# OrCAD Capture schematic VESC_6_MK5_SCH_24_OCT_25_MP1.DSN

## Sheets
1 PAGE1: size A2
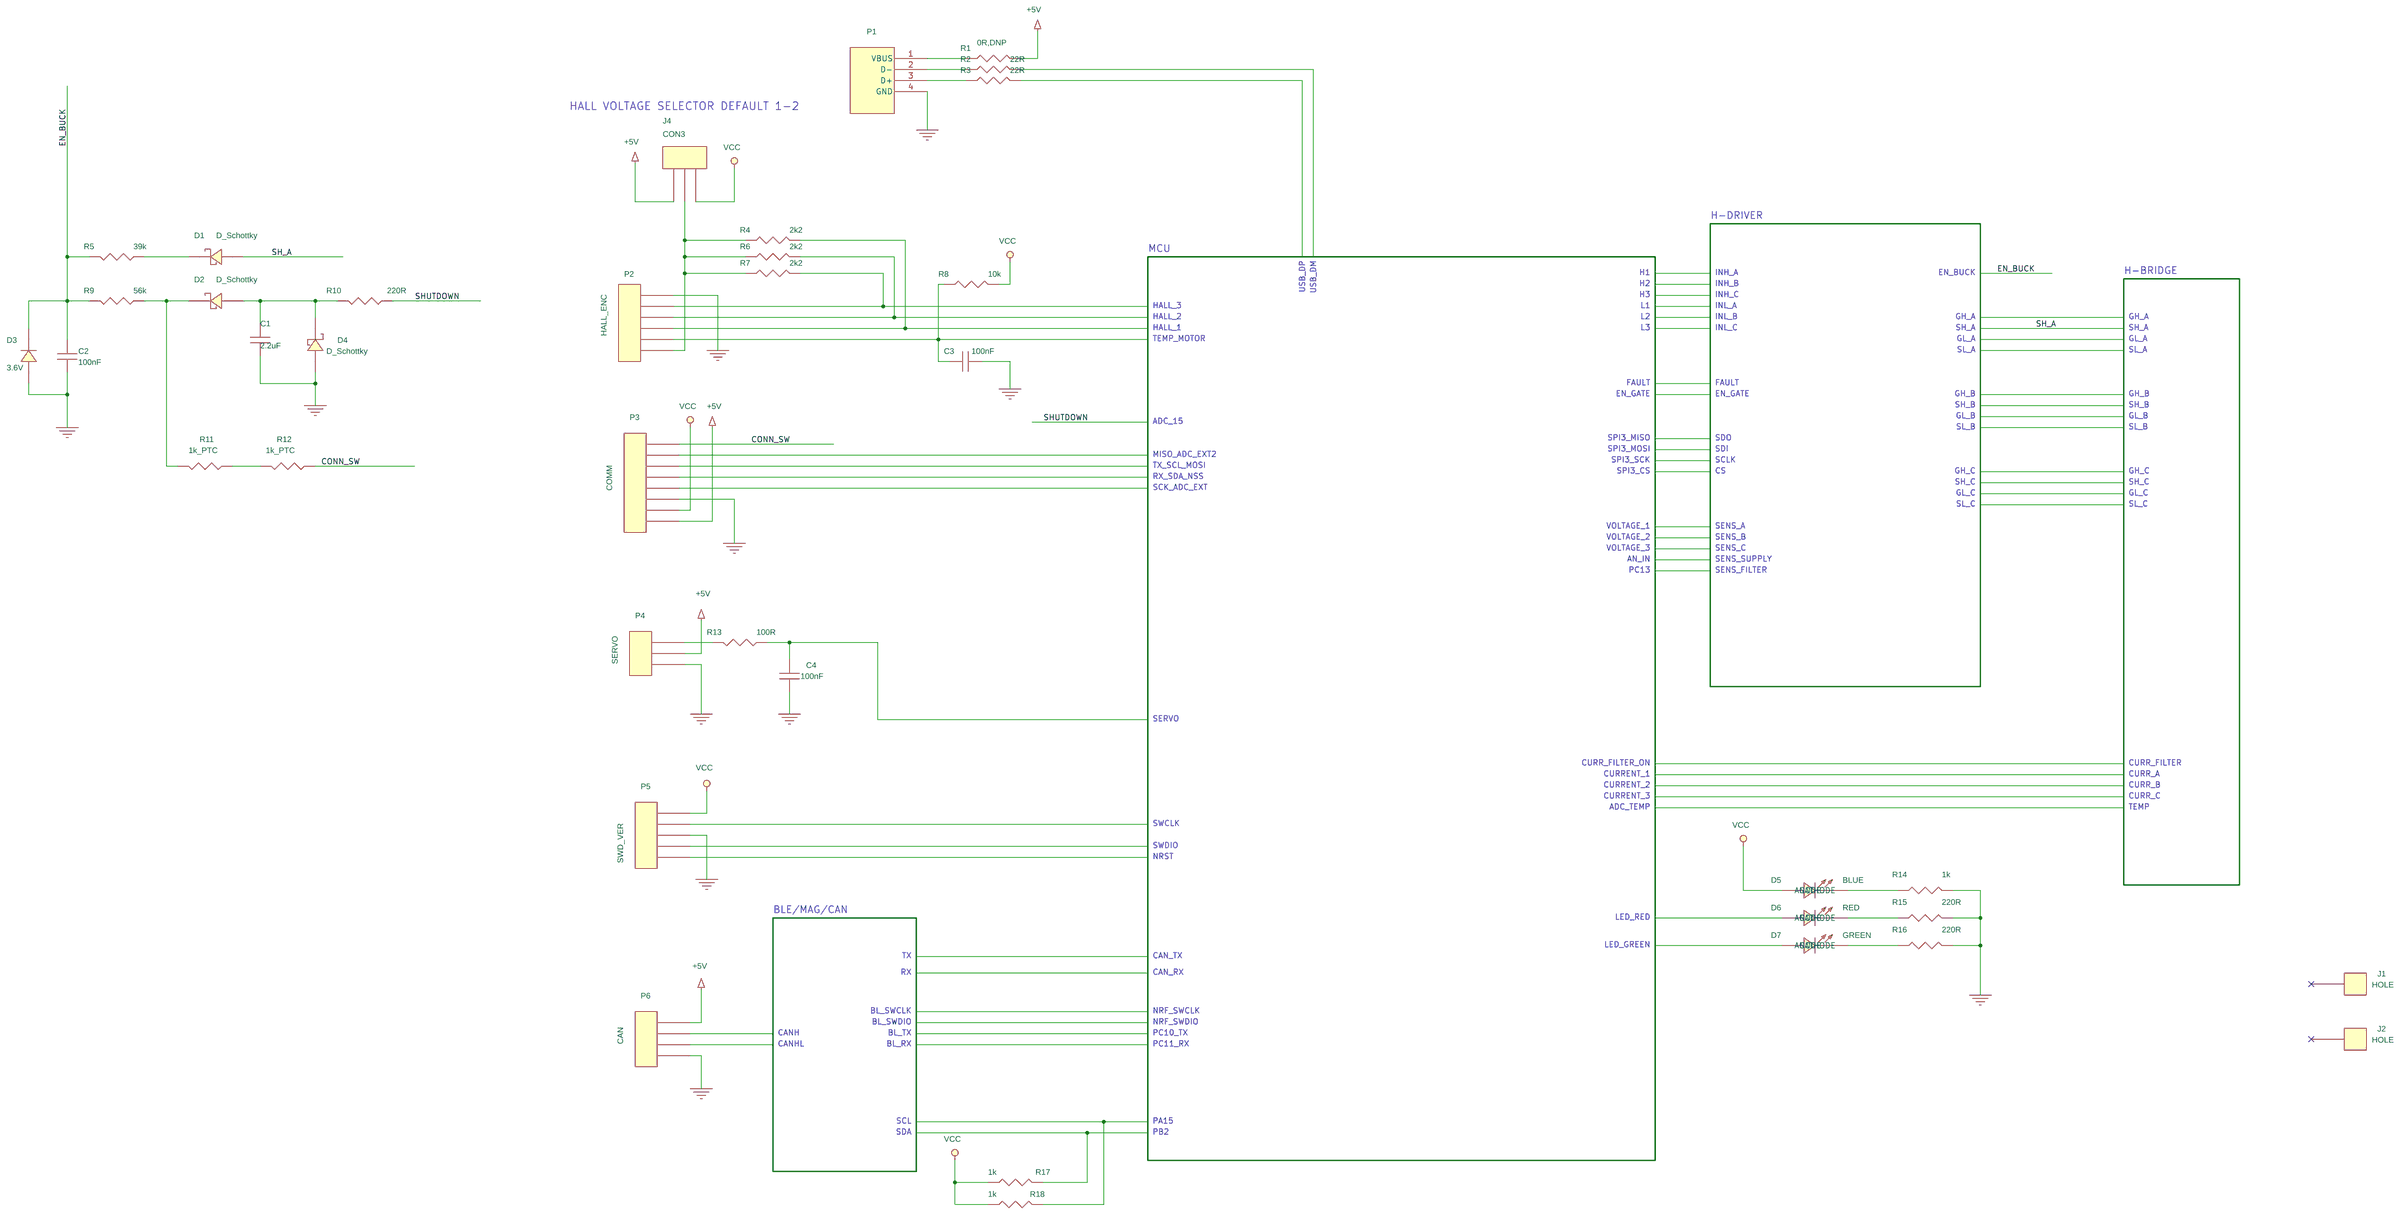
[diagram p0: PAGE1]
2 PAGE4: size A3; block H-BRIDGE
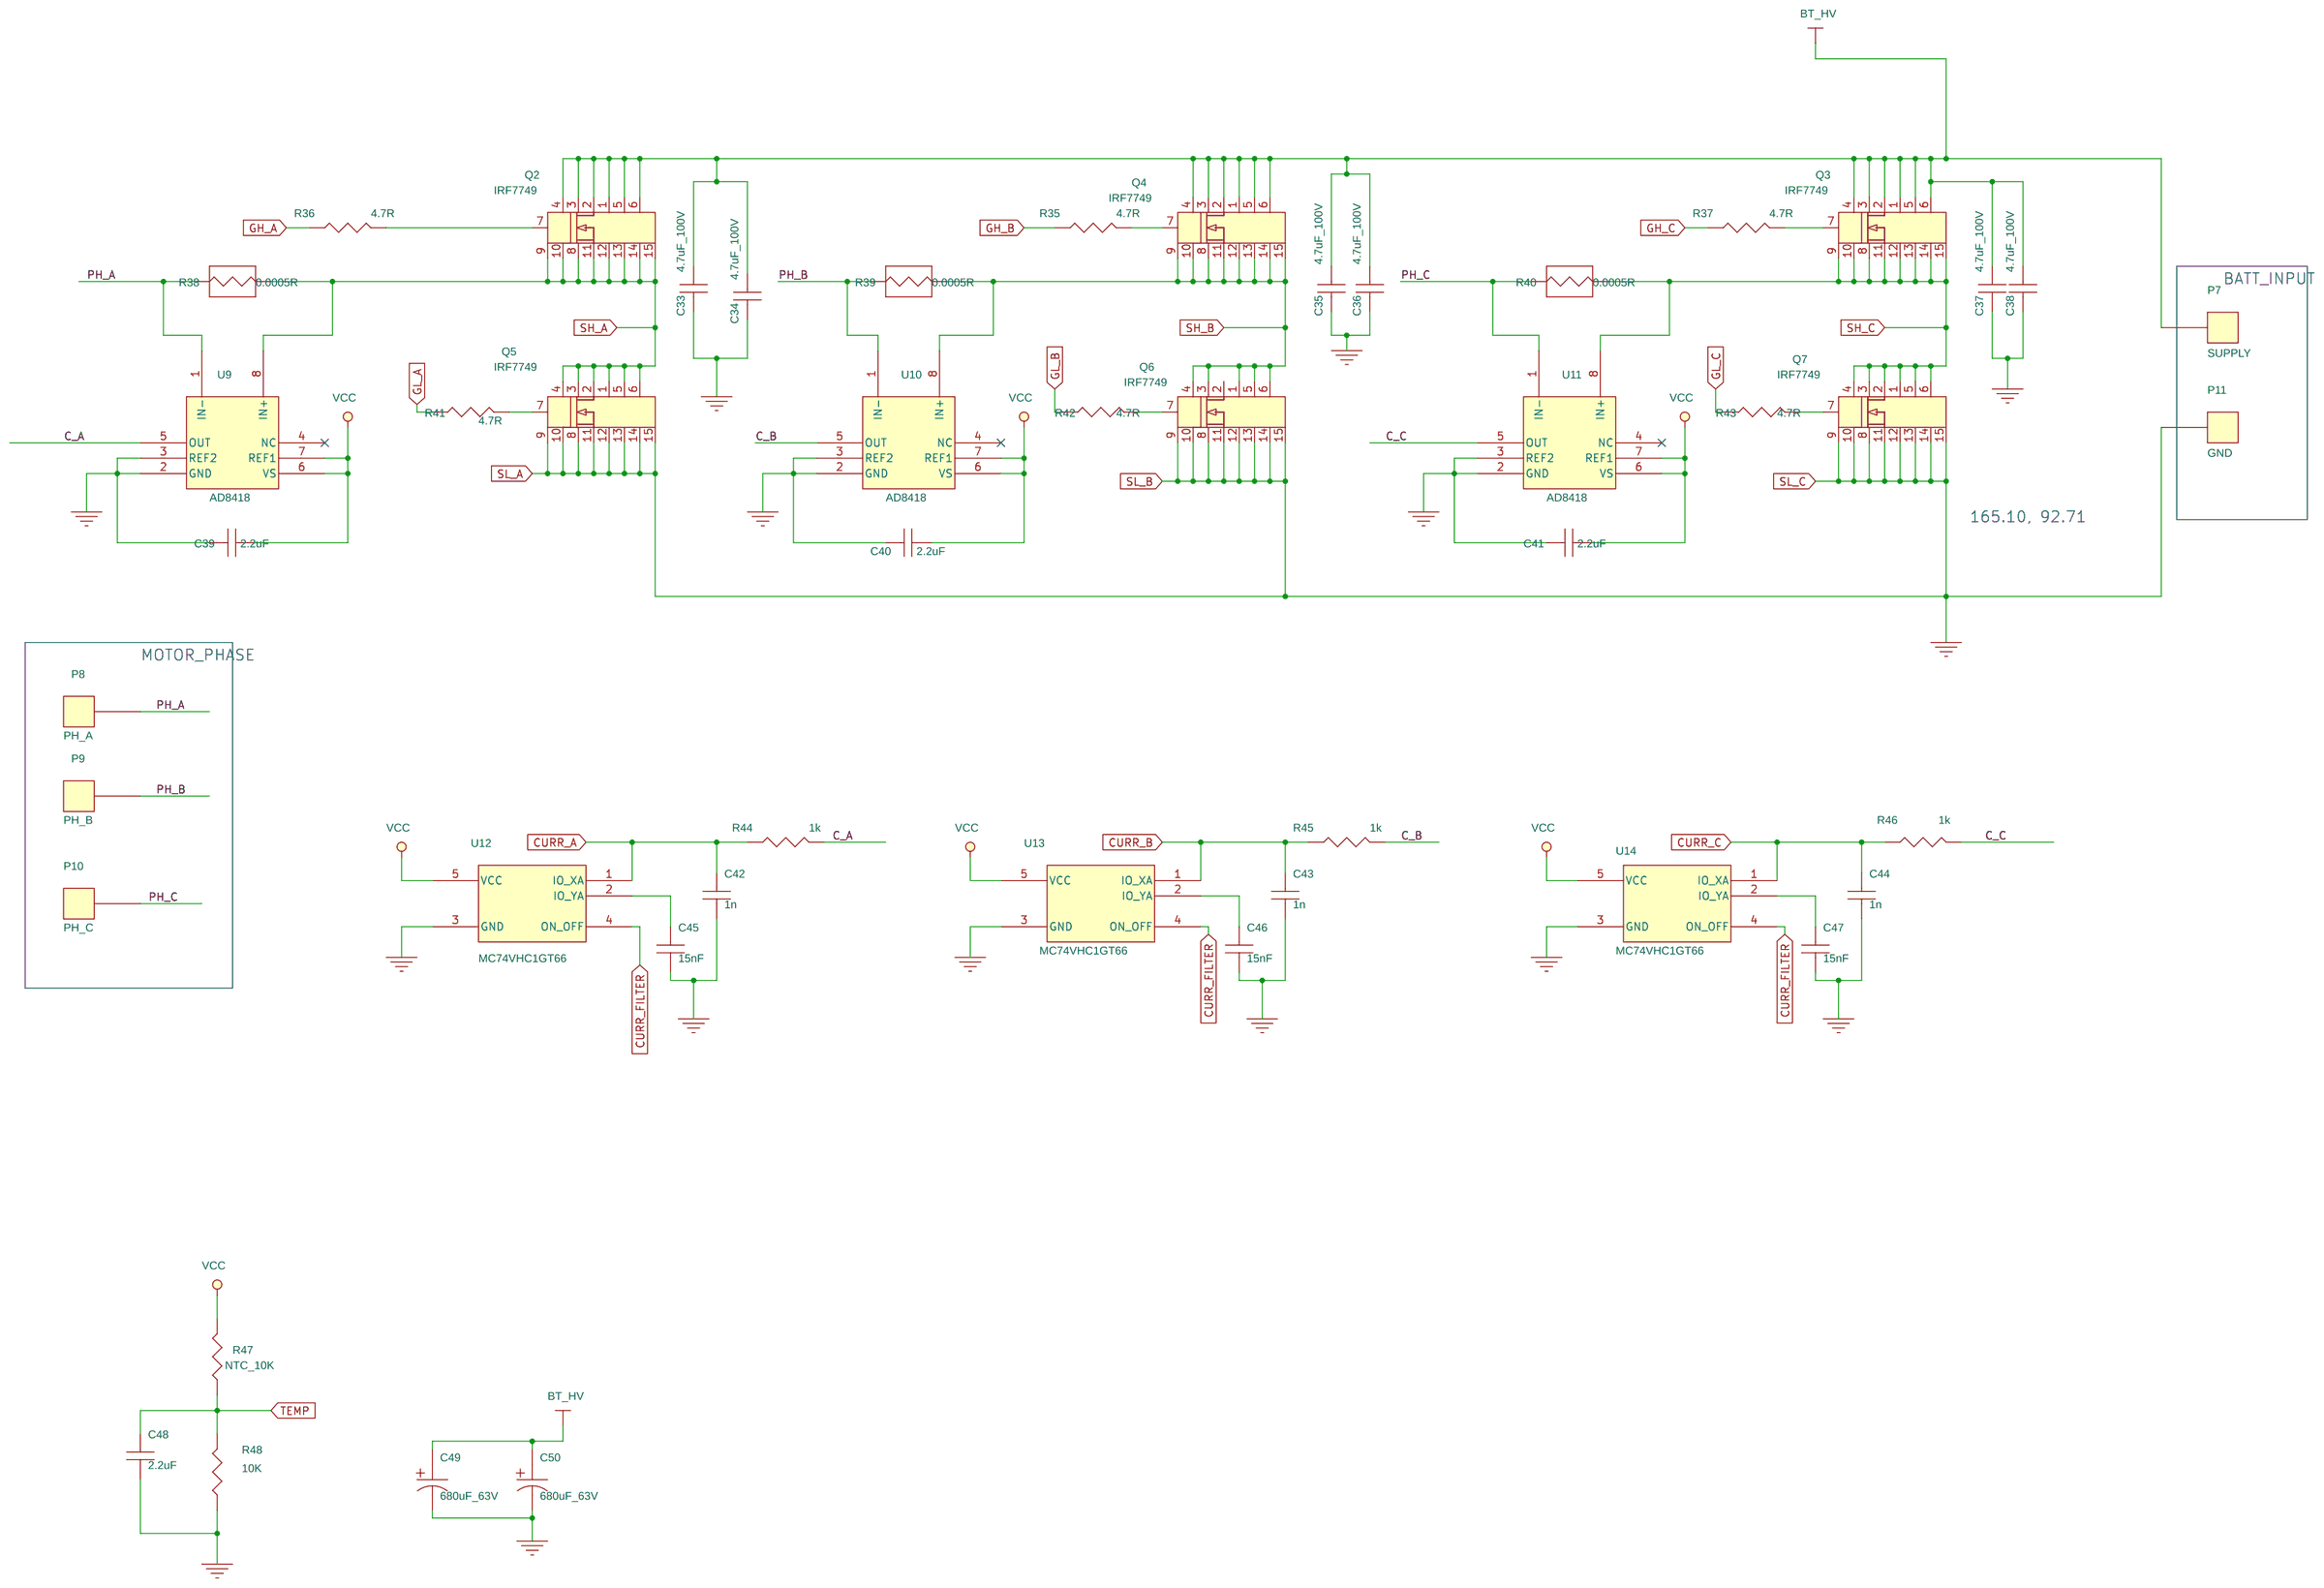
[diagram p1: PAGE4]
3 PAGE3: size A3; block H-DRIVER
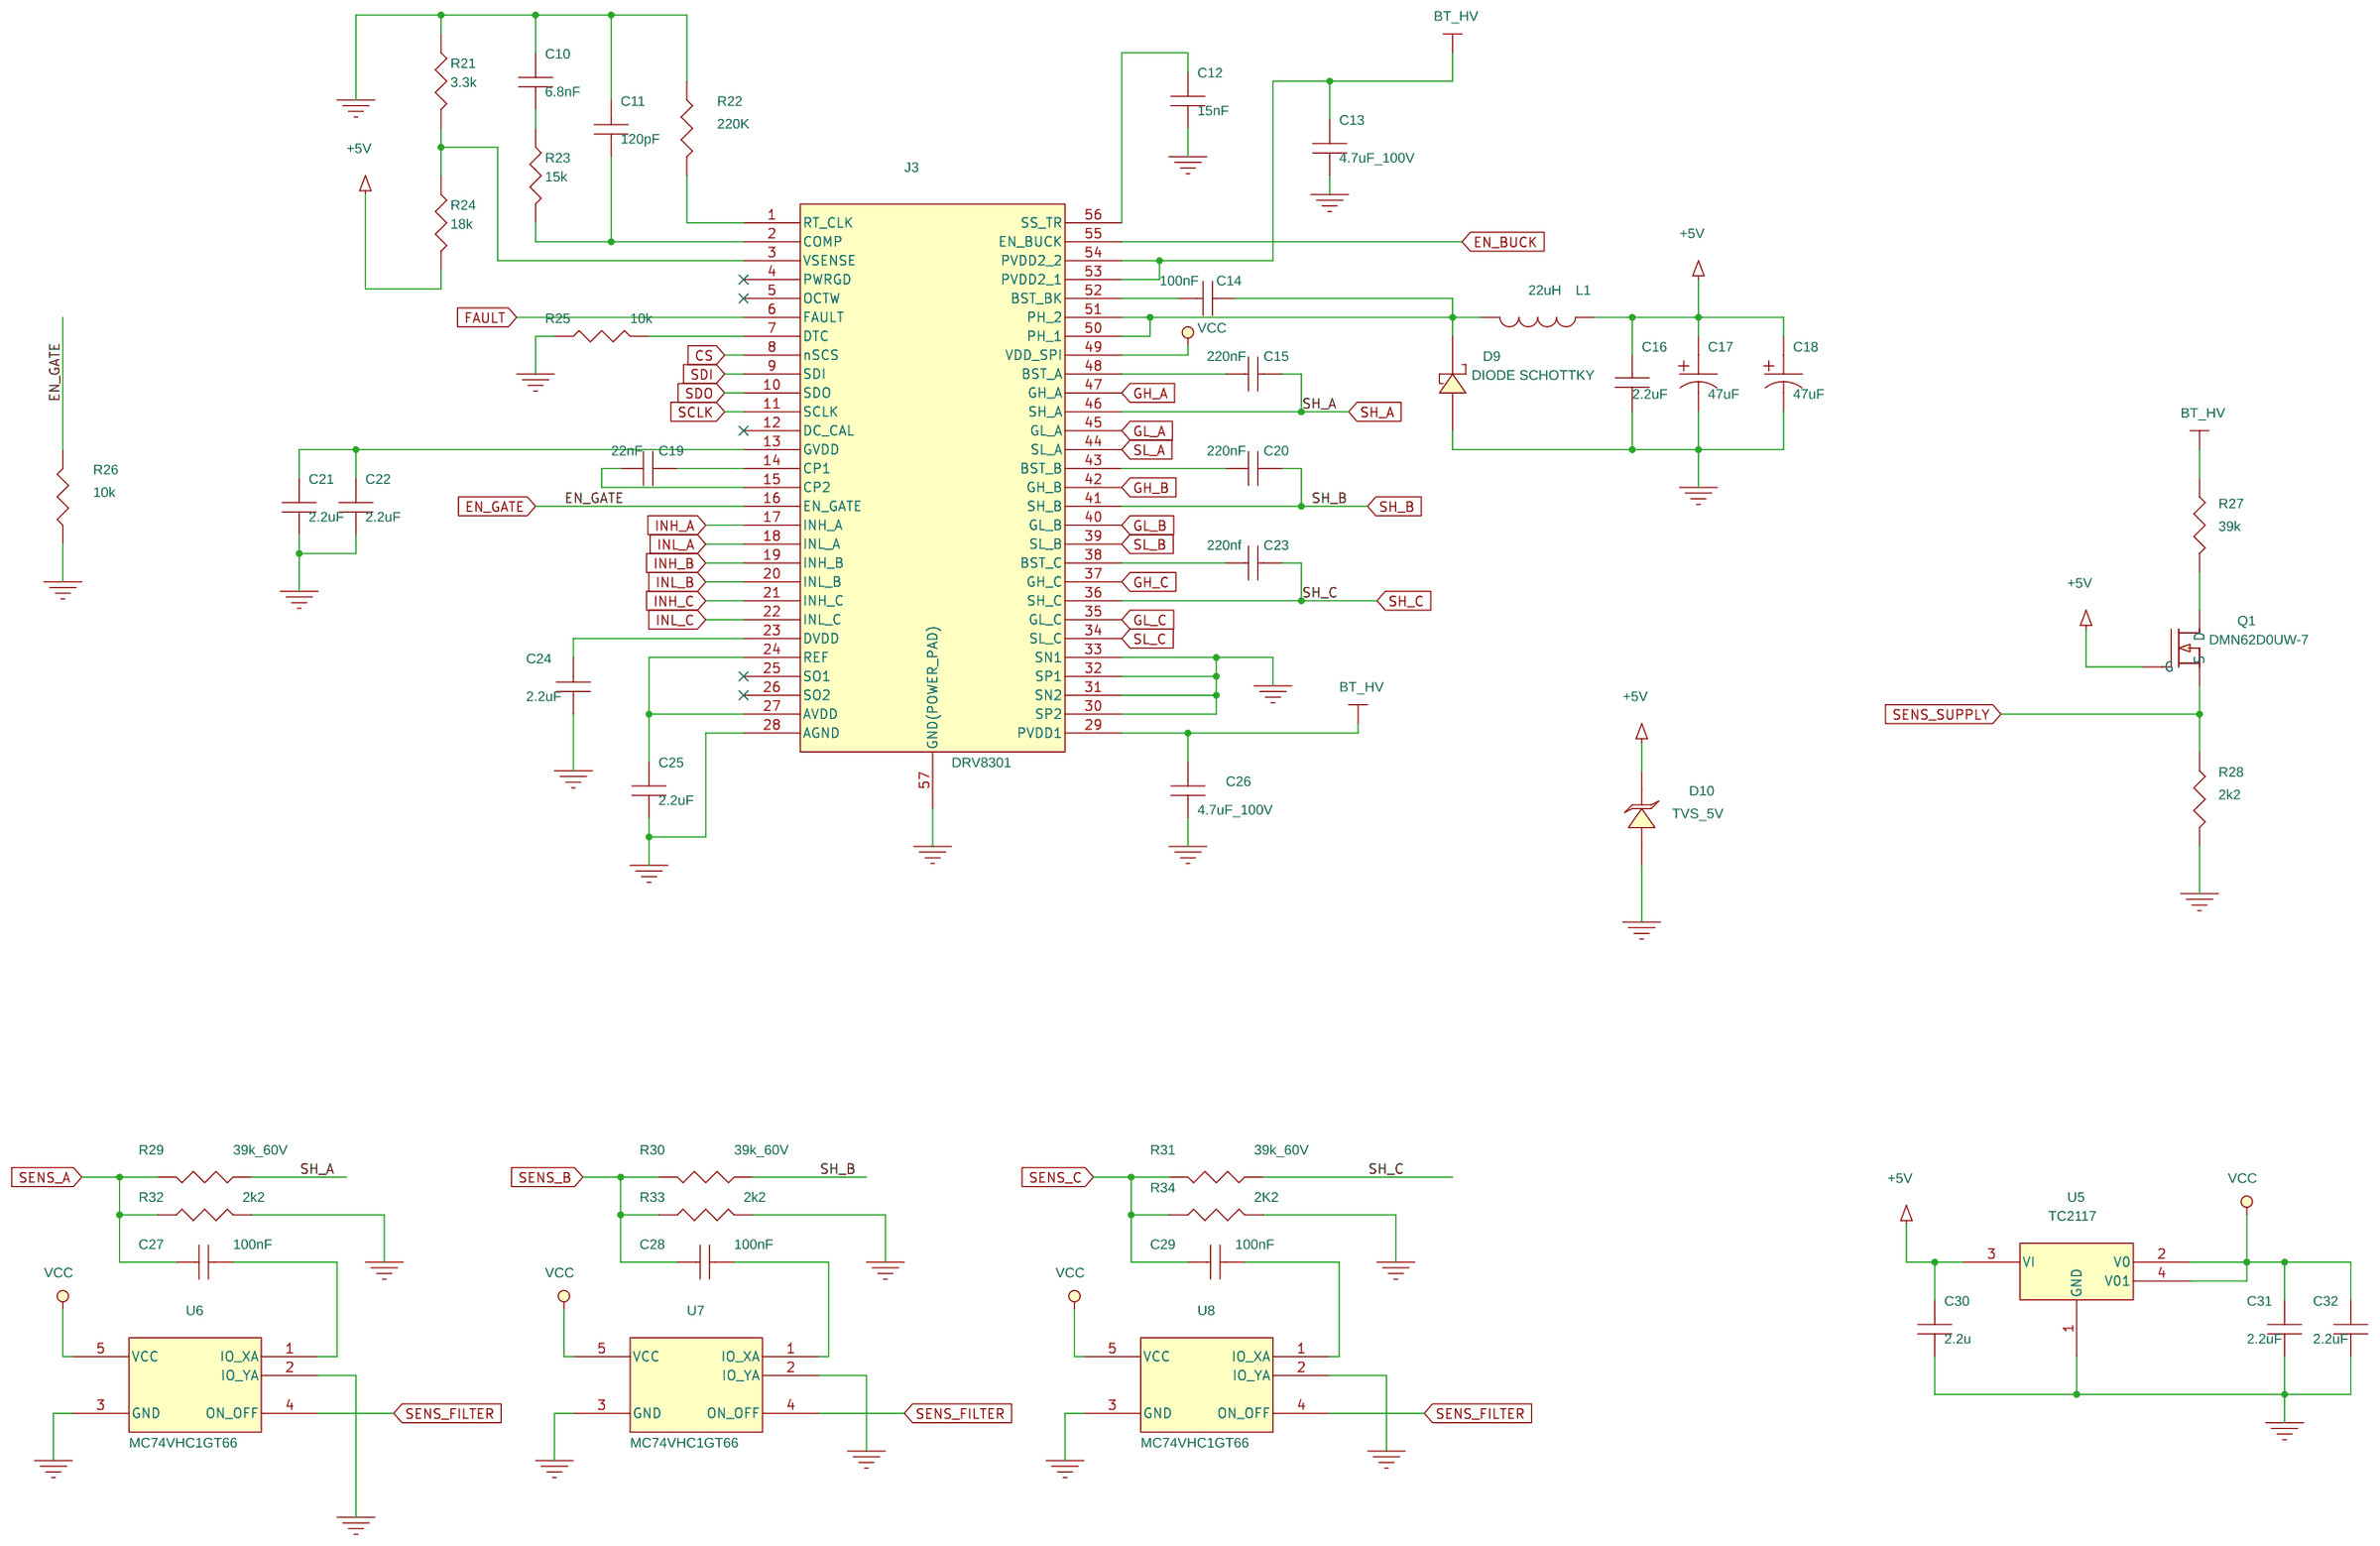
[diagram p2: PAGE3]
4 PAGE5: size A3; block MCU
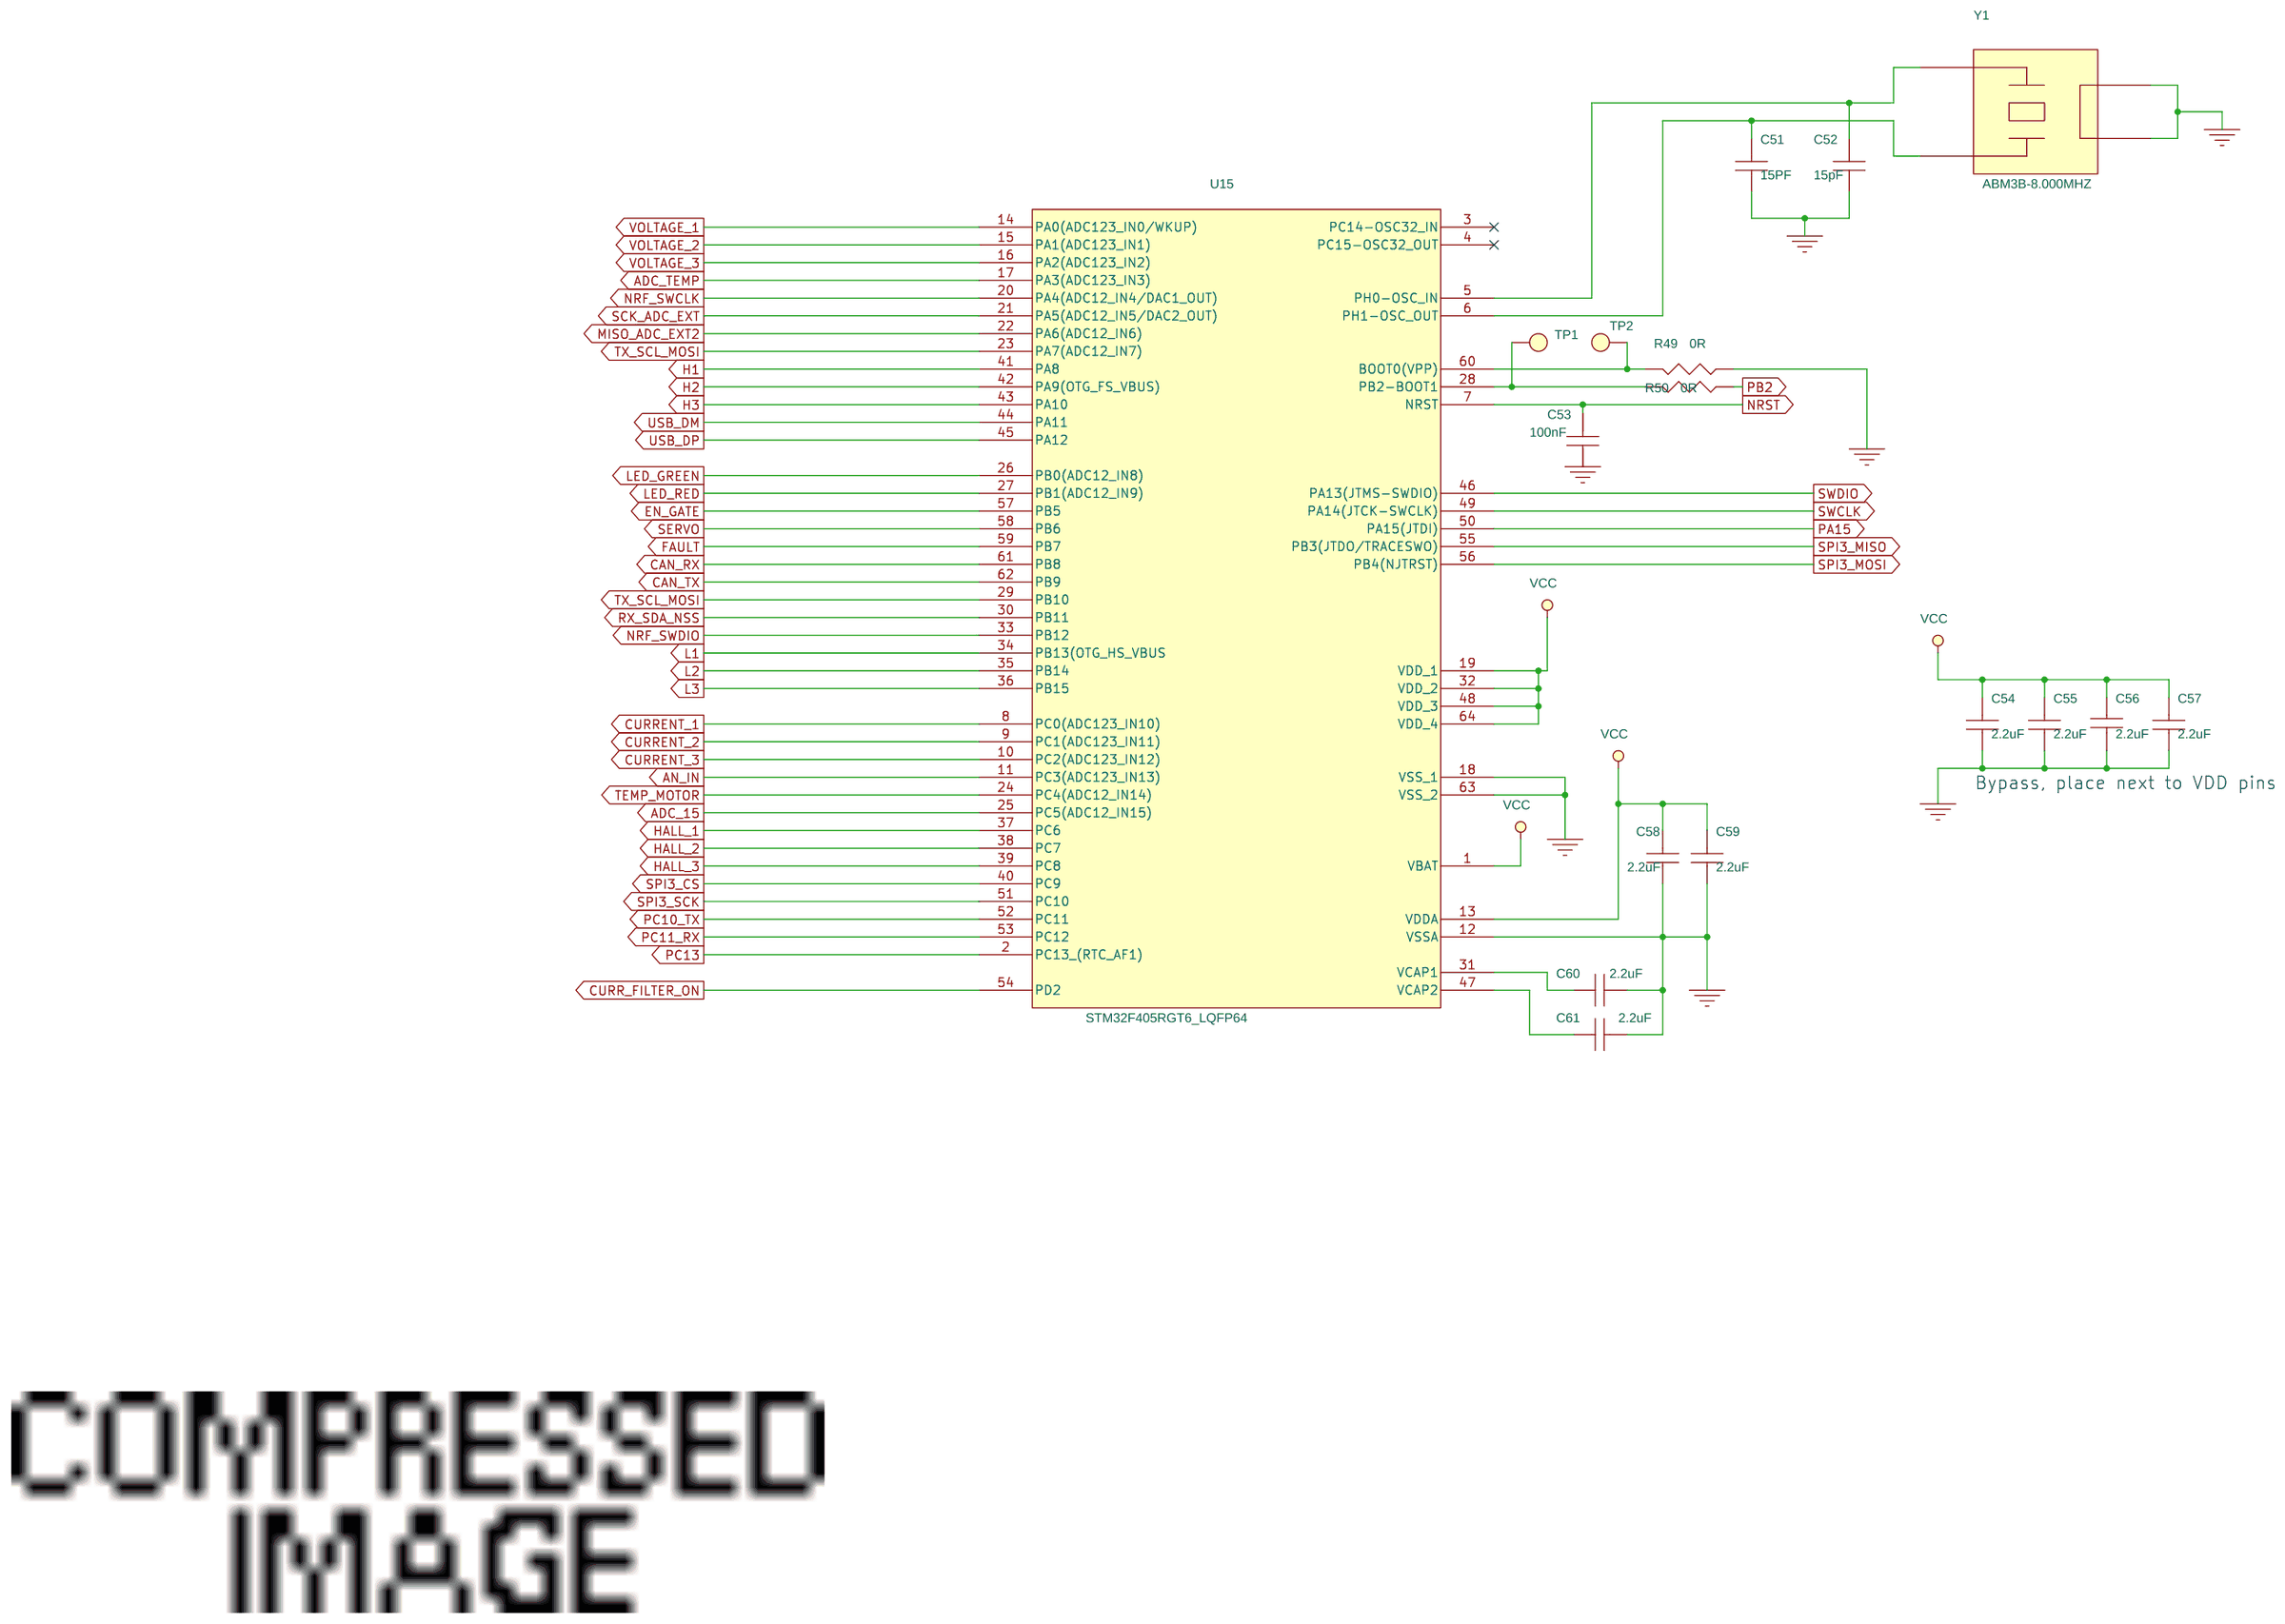
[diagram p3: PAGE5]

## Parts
sheet PAGE1
C1  2.2uF  [0805]
C2  100nF  [0603]
C3  100nF  [0603]
C4  100nF  [0603]
D1  D_Schottky  [SOD_123]
D2  D_Schottky  [SOD_323]
D3  3.6V  [SOD_123]
D4  D_Schottky  [SOD_323]
D5  BLUE  [LED_0603]
D6  RED  [LED_0603]
D7  GREEN  [LED_0603]
J1  HOLE  [MTG_3mm]
J2  HOLE  [MTG_3mm]
J4  CON3  [hdr_1x3]
P1  SWD_VER  [CON_4P_VRT_BM04BGHSTB]
P2  HALL_ENC  [CON_6P_VRT_BM06BGHSTBT]
P3  COMM  [CON_8P_VRT_BM08BGHSTBT]
P4  SERVO  [CON_3P_VRT_BM03BGHSTB]
P5  SWD_VER  [CON_5P_VRT_BM05BGHSTBT]
P6  CAN  [CON_4P_VRT_BM04BGHSTB]
R1  0R,DNP  [0603]
R2  22R  [0603]
R3  22R  [0603]
R4  2k2  [0603]
R5  39k  [0603]
R6  2k2  [0603]
R7  2k2  [0603]
R8  10k  [0603]
R9  56k  [0603]
R10  220R  [0603]
R11  1k_PTC  [0603]
R12  1k_PTC  [0603]
R13  100R  [0603]
R14  1k  [0603]
R15  220R  [0603]
R16  220R  [0603]
R17  1k  [0603]
R18  1k  [0603]
sheet PAGE3
C10  6.8nF  [0603]
C11  120pF  [0603]
C12  15nF  [0603]
C13  4.7uF_100V  [1206]
C14  100nF  [0603]
C15  220nF  [0603]
C16  2.2uF  [0805]
C17  47uF  [cap_8X10]
C18  47uF  [cap_8X10]
C19  22nF  [0603]
C20  220nF  [0603]
C21  2.2uF  [0805]
C22  2.2uF  [0805]
C23  220nf  [0603]
C24  2.2uF  [0805]
C25  2.2uF  [0805]
C26  4.7uF_100V  [1206]
C27  100nF  [0603]
C28  100nF  [0603]
C29  100nF  [0603]
C30  2.2u  [0603]
C31  2.2uF  [0805]
C32  2.2uF  [0805]
D9  DIODE SCHOTTKY  [do214aa]
D10  TVS_5V  [do-214ac]
J3  DRV8301  [HTSSOP_56P_6X14MM]
L1  22uH  [ind_7p8x7p8_sdr0805]
Q1  DMN62D0UW-7  [SOT323_3P]
R21  3.3k  [0603]
R22  220K  [0603]
R23  15k  [0603]
R24  18k  [0603]
R25  10k  [0603]
R26  10k  [0603]
R27  39k  [0603]
R28  2k2  [0603]
R29  39k_60V  [0603]
R30  39k_60V  [0603]
R31  39k_60V  [0603]
R32  2k2  [0603]
R33  2k2  [0603]
R34  2K2  [0603]
U5  TC2117  [sot223_4p]
U6  MC74VHC1GT66  [SC70_5P]
U7  MC74VHC1GT66  [SC70_5P]
U8  MC74VHC1GT66  [SC70_5P]
sheet PAGE4
C33  4.7uF_100V  [1206]
C34  4.7uF_100V  [1206]
C35  4.7uF_100V  [1206]
C36  4.7uF_100V  [1206]
C37  4.7uF_100V  [1206]
C38  4.7uF_100V  [1206]
C39  2.2uF  [0805]
C40  2.2uF  [0805]
C41  2.2uF  [0805]
C42  1n  [0603]
C43  1n  [0603]
C44  1n  [0603]
C45  15nF  [0603]
C46  15nF  [0603]
C47  15nF  [0603]
C48  2.2uF  [0805]
C49  680uF_63V  [ecap_th_12p5x35mm]
C50  680uF_63V  [ecap_th_12p5x35mm]
P7  SUPPLY  [tp_th_120mils]
P8  PH_A  [tp_th_120mils]
P9  PH_B  [tp_th_120mils]
P10  PH_C  [tp_th_120mils]
P11  GND  [tp_th_120mils]
Q2  IRF7749  [IRF7749L1TRPBF]
Q3  IRF7749  [IRF7749L1TRPBF]
Q4  IRF7749  [IRF7749L1TRPBF]
Q5  IRF7749  [IRF7749L1TRPBF]
Q6  IRF7749  [IRF7749L1TRPBF]
Q7  IRF7749  [IRF7749L1TRPBF]
R35  4.7R  [0603]
R36  4.7R  [0603]
R37  4.7R  [0603]
R38  0.0005R  [2512]
R39  0.0005R  [2512]
R40  0.0005R  [2512]
R41  4.7R  [0603]
R42  4.7R  [0603]
R43  4.7R  [0603]
R44  1k  [0603]
R45  1k  [0603]
R46  1k  [0603]
R47  NTC_10K  [0603]
R48  10K  [0603]
U9  AD8418  [msop8]
U10  AD8418  [msop8]
U11  AD8418  [msop8]
U12  MC74VHC1GT66  [SC70_5P]
U13  MC74VHC1GT66  [SC70_5P]
U14  MC74VHC1GT66  [SC70_5P]
sheet PAGE5
C51  15PF  [0603]
C52  15pF  [0603]
C53  100nF  [0603]
C54  2.2uF  [0805]
C55  2.2uF  [0805]
C56  2.2uF  [0805]
C57  2.2uF  [0805]
C58  2.2uF  [0805]
C59  2.2uF  [0805]
C60  2.2uF  [0805]
C61  2.2uF  [0805]
R49  0R  [0603]
R50  0R  [0603]
TP1  T POINT R  [TP_50MIL]
TP2  T POINT R  [TP_50MIL]
U15  STM32F405RGT6_LQFP64  [lqfp64_10x10mm]
Y1  ABM3B-8.000MHZ  [XTAL_4P_5X3P2MM_ABM3B]

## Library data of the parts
C1 C16 C21 C22 C24 C25 C31 C32 C39-C41 C48 C54-C61 = CAP_NP: Manufacturer: TDK; Mfg_Num: C2012X7R1H225K125AE
C2-C4 C10-C12 C14 C15 C19 C20 C23 C27-C30 C42-C47 C53 = CAP_NP
D1 = DIODE_SCHOTTKY_0: Manufacturer: onsemi; Mfg_Num: MMSD4148T1G
D2 D4 = DIODE_SCHOTTKY_0: Manufacturer: Diodes Incorporated; Mfg_Num: BAT54WS
D3 = DIODE31_0: Manufacturer: Diodes Incorporated; Mfg_Num: MMSZ5232B
D5-D7 = LED_3
J1 J2 P7-P11 = CON1
J4 = CON3_1
P1 = CON6A_8: Manufacturer: JST Sales America Inc.; Mfg_Num: BM04B-GHS-TBT
P2 = CON6_0: Mfg_Num: BM06B-GHS-TBT
P3 = CON8: Mfg_Num: BM08B-GHS-TBT
P4 = CON3: Mfg_Num: BM03B-GHS-TBT
P5 = CON5: Manufacturer: JST Sales America Inc.; Mfg_Num: BM05B-GHS-TBT
P6 = CON4_0: Mfg_Num: BM04B-GHS-TBT
R1-R18 R21-R37 R41-R50 = R
C13 C26 C33-C38 = CAP_NP: Manufacturer: Murata Electronics; Mfg_Num: GRJ31CZ72A475ME01L
C17 C18 = CAP_POL_0: Manufacturer: Nichicon; Mfg_Num: UCX1H470MCL1GS
D9 = DIODE_SCHOTTKY_1: Manufacturer: Nexperia; Mfg_Num: PMEG6020ER,115
D10 = DIODE_TVS_0: Manufacturer: Littelfuse; Mfg_Num: SMAJ5.0A
J3 = CON58_3: Manufacturer: Texas Instruments; Mfg_Num: DRV8301DCAR
L1 = INDUCTOR: Manufacturer: Bourns; Mfg_Num: SDR0805-220ML
Q1 = MOSFET_N_3: Manufacturer: Diodes Incorporated
U5 = CON2AP_4: Manufacturer: Microchip Technology; Mfg_Num: TC2117-3.3VDBTR
U6-U8 U12-U14 = CON6A_5: Manufacturer: onsemi; Mfg_Num: MC74VHC1GT66DFT1
C49 C50 = CAP_POL_0: Mfg_Num: EKY630ELL681MK40S
Q2-Q4 Q7 = MOSFET_N_5: Manufacturer: Infineon
Q5 Q6 = MOSFET_N_5: Manufacturer: Infineon; Mfg_Num: IRF7749L1TRPB
R38-R40 = R_3: Manufacturer: Bourns; Mfg_Num: CSS2H-2512R-L500F
U9-U11 = CON8A_5: Manufacturer: Analog Devices Inc; Mfg_Num: AD8418AWBRMZ
C51 C52 = CAP_NP: Manufacturer: Murata Electronics; Mfg_Num: GRM1885C2A150JA01D
TP1 TP2 = T_POINT_R
U15 = CON60_5: Manufacturer: STMicroelectronics
Y1 = CRYSTAL1-4_SM_9: Manufacturer: ABRACON; Mfg_Num: ABM3B-8.000MHZ-10-1-U-T

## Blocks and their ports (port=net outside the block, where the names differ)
H-BRIDGE = schematic H-Bridge, on sheet PAGE1: GL_A=N483651, SH_A, SL_A=0, SH_B=N496273, GL_B=N496277, SL_B=0, SH_C=N496289, GH_C=N496285, SL_C=0, GL_C=N496293, GH_B=N496269, CURR_C=N495765, CURR_B=N495753, CURR_A=N495741, CURR_FILTER=N495729, TEMP=N495777, GH_A=N483635
MCU = schematic MCU, on sheet PAGE1: SCK_ADC_EXT=N492258, MISO_ADC_EXT2=N492162, TX_SCL_MOSI=N492166, H1=N494356, H2=N494360, VOLTAGE_1=N495709, VOLTAGE_2=N495713, VOLTAGE_3=N495717, ADC_TEMP=N495777, NRF_SWCLK=N490496, H3=N494364, USB_DM=N421455, USB_DP=N421471, LED_GREEN=N317096, CAN_TX=N490262, RX_SDA_NSS=N492170, NRF_SWDIO=N490506, L1=N494368, LED_RED=N317032, EN_GATE=N494760, SERVO=N119428, FAULT=N494756, CAN_RX=N490274, L2=N494372, L3=N494376, CURRENT_1=N495741, CURRENT_2=N495753, HALL_2=N114106, HALL_3=N114102, SPI3_CS=N495168, SPI3_SCK=N495164, PC10_TX=N490510, CURRENT_3=N495765, AN_IN=N495721, TEMP_MOTOR=N114114, ADC_15=SHUTDOWN, HALL_1=N114110, PC11_RX=N490514, PC13=N495725, CURR_FILTER_ON=N495729, SWDIO=N316068, SWCLK=N316048, PA15=N488738, SPI3_MISO=N495156, SPI3_MOSI=N495160, NRST=N316080, PB2=N488742
BLE/MAG/CAN = schematic , on sheet PAGE1: SDA=N488742, SCL=N488738, TX=N490262, RX=N490274, CANH=N488558, CANHL=N488562, BL_TX=N490510, BL_RX=N490514, BL_SWCLK=N490496, BL_SWDIO=N490506
H-DRIVER = schematic Driver, on sheet PAGE1: FAULT=N494756, CS=N495168, SDI=N495160, SDO=N495156, SCLK=N495164, EN_GATE=N494760, INH_A=N494356, INL_A=N494368, INH_B=N494360, INL_B=N494372, INH_C=N494364, INL_C=N494376, EN_BUCK, GH_A=N483635, GL_A=N483651, SL_A=0, GH_B=N496269, GL_B=N496277, SL_B=0, GH_C=N496285, GL_C=N496293, SL_C=0, SH_C=N496289, SH_B=N496273, SH_A, SENS_A=N495709, SENS_B=N495713, SENS_C=N495717, SENS_FILTER=N495725, SENS_SUPPLY=N495721

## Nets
+5V: C16.1 C17.P C18.P C30.2 D10.K(CATHODE) J4.1 L1.1 P3.1 P4.2 P6.4 Q1.1(G) R1.2 R24.2 U5.3(VI)
VCC: C31.2 C32.2 C39.2 C40.2 C41.2 C54.2 C55.2 C56.1 C57.2 C58.2 C59.2 D5.A(ANODE) J3.49(VDD_SPI) J4.3 P3.2 P5.5 R8.2 R17.2 R18.2 R47.2 U5.2(V0) U5.4(V01) U6.5(VCC) U7.5(VCC) U8.5(VCC) U9.6(VS) U9.7(REF1) U10.6(VS) U10.7(REF1) U11.6(VS) U11.7(REF1) U12.5(VCC) U13.5(VCC) U14.5(VCC) U15.1(VBAT) U15.13(VDDA) U15.19(VDD_1) U15.32(VDD_2) U15.48(VDD_3) U15.64(VDD_4)
0: C1.1 C2.1 C3.2 C4.1 C10.2 C11.2 C12.1 C13.1 C16.2 C17.N C18.N C21.1 C22.1 C24.1 C25.1 C26.1 C30.1 C31.1 C32.1 C33.2 C34.2 C35.2 C36.2 C37.2 C38.2 C39.1 C40.1 C41.1 C42.2 C43.2 C44.2 C45.2 C46.2 C47.2 C48.2 C49.N C50.N C51.1 C52.1 C53.1 C54.1 C55.1 C56.2 C57.1 C58.1 C59.1 C60.2 C61.2 D3.A D4.A(ANODE) D9.A(ANODE) D10.A(ANODE) J3.28(AGND) J3.30(SP2) J3.31(SN2) J3.32(SP1) J3.33(SN1) J3.34(SL_C) J3.39(SL_B) J3.44(SL_A) J3.57(GND(POWER_PAD)) P1.4(GND) P2.1 P3.3 P4.1 P5.3 P6.1 P11.1 Q5.8(S1) Q5.9(S2) Q5.10(S3) Q5.11(S4) Q5.12(S5) Q5.13(S6) Q5.14(S7) Q5.15(S8) Q6.8(S1) Q6.9(S2) Q6.10(S3) Q6.11(S4) Q6.12(S5) Q6.13(S6) Q6.14(S7) Q6.15(S8) Q7.8(S1) Q7.9(S2) Q7.10(S3) Q7.11(S4) Q7.12(S5) Q7.13(S6) Q7.14(S7) Q7.15(S8) R14.2 R15.2 R16.2 R21.1 R22.1 R25.1 R26.1 R28.2 R32.2 R33.2 R34.2 R48.1 R49.1 U5.1(GND) U6.2(IO_YA) U6.3(GND) U7.2(IO_YA) U7.3(GND) U8.2(IO_YA) U8.3(GND) U9.2(GND) U9.3(REF2) U10.2(GND) U10.3(REF2) U11.2(GND) U11.3(REF2) U12.3(GND) U13.3(GND) U14.3(GND) U15.12(VSSA) U15.18(VSS_1) U15.63(VSS_2) Y1.2 Y1.4
BT_HV: C13.2 C26.2 C33.1 C34.1 C35.1 C36.1 C37.1 C38.1 C49.P C50.P J3.29(PVDD1) J3.53(PVDD2_1) J3.54(PVDD2_2) P7.1 Q2.1(D1) Q2.2(D2) Q2.3(D3) Q2.4(D4) Q2.5(D5) Q2.6(D6) Q3.1(D1) Q3.2(D2) Q3.3(D3) Q3.4(D4) Q3.5(D5) Q3.6(D6) Q4.1(D1) Q4.2(D2) Q4.3(D3) Q4.4(D4) Q4.5(D5) Q4.6(D6) R27.1
CONN_SW: P3.8 R12.1
EN_BUCK: C2.2 D3.K J3.55(EN_BUCK) R5.2 R9.2
H-BRIDGE/C_A: R44.2 U9.5(OUT)
H-BRIDGE/C_B: R45.2 U10.5(OUT)
H-BRIDGE/C_C: R46.2 U11.5(OUT)
H-BRIDGE/PH_A: P8.1 R38.1 U9.1(IN-)
H-BRIDGE/PH_B: P9.1 R39.1 U10.1(IN-)
H-BRIDGE/PH_C: P10.1 R40.1 U11.1(IN-)
SH_A: C15.2 D1.A(ANODE) J3.46(SH_A) Q2.8(S1) Q2.9(S2) Q2.10(S3) Q2.11(S4) Q2.12(S5) Q2.13(S6) Q2.14(S7) Q2.15(S8) Q5.1(D1) Q5.2(D2) Q5.3(D3) Q5.4(D4) Q5.5(D5) Q5.6(D6) R29.1 R38.2 U9.8(IN+)
SHUTDOWN: R10.1 U15.25(PC5(ADC12_IN15))
H-BRIDGE/N399081: Q5.7(G) R41.2
H-BRIDGE/N399151: Q2.7(G) R36.2
H-BRIDGE/N405714: Q4.7(G) R35.2
H-BRIDGE/N405958: Q6.7(G) R42.2
H-BRIDGE/N406713: Q3.7(G) R37.2
H-BRIDGE/N406957: Q7.7(G) R43.2
H-BRIDGE/N413411: C45.1 U12.2(IO_YA)
H-BRIDGE/N415177: C46.1 U13.2(IO_YA)
H-BRIDGE/N415727: C47.1 U14.2(IO_YA)
H-DRIVER/N382210: C12.2 J3.56(SS_TR)
H-DRIVER/N382270: C10.1 R23.1
H-DRIVER/N382306: J3.3(VSENSE) R21.2 R24.1
H-DRIVER/N382374: C11.1 J3.2(COMP) R23.2
H-DRIVER/N382386: J3.1(RT_CLK) R22.2
H-DRIVER/N382652: C14.2 J3.52(BST_BK)
H-DRIVER/N382656: C14.1 D9.K(CATHODE) J3.50(PH_1) J3.51(PH_2) L1.2
H-DRIVER/N382740: J3.7(DTC) R25.2
H-DRIVER/N382848: C15.1 J3.48(BST_A)
H-DRIVER/N382956: C21.2 C22.2 J3.13(GVDD)
H-DRIVER/N383040: C19.2 J3.14(CP1)
H-DRIVER/N383044: C20.1 J3.43(BST_B)
H-DRIVER/N383064: C19.1 J3.15(CP2)
H-DRIVER/N383228: C23.1 J3.38(BST_C)
H-DRIVER/N383264: Q1.3(D) R27.2
H-DRIVER/N383316: C24.2 J3.23(DVDD)
H-DRIVER/N383358: C25.2 J3.24(REF) J3.27(AVDD)
H-DRIVER/N453854: C27.2 U6.1(IO_XA)
H-DRIVER/N453874: C28.2 U7.1(IO_XA)
H-DRIVER/N453894: C29.2 U8.1(IO_XA)
MCU/N379550: C60.1 U15.31(VCAP1)
MCU/N379578: C61.1 U15.47(VCAP2)
MCU/N440238: C52.2 U15.5(PH0-OSC_IN) Y1.1
MCU/N440256: C51.2 U15.6(PH1-OSC_OUT) Y1.3
MCU/N475951: R49.2 TP2.1(TP) U15.60(BOOT0(VPP))
MCU/N476249: R50.2 TP1.1(TP) U15.28(PB2-BOOT1)
N113958: J4.2 P2.6 R4.1 R6.1 R7.1
N114102: P2.2 R7.2 U15.39(PC8)
N114106: P2.3 R6.2 U15.38(PC7)
N114110: P2.4 R4.2 U15.37(PC6)
N114114: C3.1 P2.5 R8.1 U15.24(PC4(ADC12_IN14))
N119424: P4.3 R13.2
N119428: C4.2 R13.1 U15.58(PB6)
N316048: P5.4 U15.49(PA14(JTCK-SWCLK))
N316068: P5.2 U15.46(PA13(JTMS-SWDIO))
N316080: C53.2 P5.1 U15.7(NRST)
N316972: D5.K(CATHODE) R14.1
N317032: D6.A(ANODE) U15.27(PB1(ADC12_IN9))
N317036: D6.K(CATHODE) R15.1
N317096: D7.A(ANODE) U15.26(PB0(ADC12_IN8))
N317100: D7.K(CATHODE) R16.1
N320425: D2.K(CATHODE) R9.1 R11.2
N320494: R11.1 R12.2
N320696: C1.2 D2.A(ANODE) D4.K(CATHODE) R10.2
N321457: D1.K(CATHODE) R5.1
N421403: P1.1(VBUS) R1.1
N421435: P1.2(D-) R2.1
N421455: R2.2 U15.44(PA11)
N421467: P1.3(D+) R3.1
N421471: R3.2 U15.45(PA12)
N483635: J3.47(GH_A) R36.1
N483651: J3.45(GL_A) R41.1
N488738: R18.1 U15.50(PA15(JTDI))
N488742: R17.1 R50.1
N492162: P3.7 U15.22(PA6(ADC12_IN6))
N492166: P3.6 U15.23(PA7(ADC12_IN7)) U15.29(PB10)
N492170: P3.5 U15.30(PB11)
N492258: P3.4 U15.21(PA5(ADC12_IN5/DAC2_OUT))
N494356: J3.17(INH_A) U15.41(PA8)
N494360: J3.19(INH_B) U15.42(PA9(OTG_FS_VBUS))
N494364: J3.21(INH_C) U15.43(PA10)
N494368: J3.18(INL_A) U15.34(PB13(OTG_HS_VBUS)
N494372: J3.20(INL_B) U15.35(PB14)
N494376: J3.22(INL_C) U15.36(PB15)
N494756: J3.6(FAULT) U15.59(PB7)
N494760: J3.16(EN_GATE) R26.2 U15.57(PB5)
N495156: J3.10(SDO) U15.55(PB3(JTDO/TRACESWO))
N495160: J3.9(SDI) U15.56(PB4(NJTRST))
N495164: J3.11(SCLK) U15.51(PC10)
N495168: J3.8(nSCS) U15.40(PC9)
N495709: C27.1 R29.2 R32.1 U15.14(PA0(ADC123_IN0/WKUP))
N495713: C28.1 R30.2 R33.1 U15.15(PA1(ADC123_IN1))
N495717: C29.1 R31.2 R34.1 U15.16(PA2(ADC123_IN2))
N495721: Q1.2(S) R28.1 U15.11(PC3(ADC123_IN13))
N495725: U6.4(ON_OFF) U7.4(ON_OFF) U8.4(ON_OFF) U15.2(PC13_(RTC_AF1))
N495729: U12.4(ON_OFF) U13.4(ON_OFF) U14.4(ON_OFF) U15.54(PD2)
N495741: C42.1 R44.1 U12.1(IO_XA) U15.8(PC0(ADC123_IN10))
N495753: C43.1 R45.1 U13.1(IO_XA) U15.9(PC1(ADC123_IN11))
N495765: C44.1 R46.1 U14.1(IO_XA) U15.10(PC2(ADC123_IN12))
N495777: C48.1 R47.1 R48.2 U15.17(PA3(ADC123_IN3))
N496269: J3.42(GH_B) R35.1
N496273: C20.2 J3.41(SH_B) Q4.8(S1) Q4.9(S2) Q4.10(S3) Q4.11(S4) Q4.12(S5) Q4.13(S6) Q4.14(S7) Q4.15(S8) Q6.1(D1) Q6.3(D3) Q6.4(D4) Q6.5(D5) Q6.6(D6) R30.1 R39.2 U10.8(IN+)
N496277: J3.40(GL_B) R42.1
N496285: J3.37(GH_C) R37.1
N496289: C23.2 J3.36(SH_C) Q3.8(S1) Q3.9(S2) Q3.10(S3) Q3.11(S4) Q3.12(S5) Q3.13(S6) Q3.14(S7) Q3.15(S8) Q7.1(D1) Q7.2(D2) Q7.3(D3) Q7.4(D4) Q7.5(D5) Q7.6(D6) R31.1 R40.2 U11.8(IN+)
N496293: J3.35(GL_C) R43.1

Not connected (* = marked no-connect by the designer): J1 1*; J2 1*; J3 4(PWRGD)* 5(OCTW)* 12(DC_CAL)* 25(SO1)* 26(SO2)*; P6 2 3; Q6 2(D2); U9 4(NC)*; U10 4(NC)*; U11 4(NC)*; U15 3(PC14-OSC32_IN)* 4(PC15-OSC32_OUT)* 20(PA4(ADC12_IN4/DAC1_OUT)) 33(PB12) 52(PC11) 53(PC12) 61(PB8) 62(PB9)

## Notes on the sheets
sheet 1
- HALL VOLTAGE SELECTOR DEFAULT 1-2
sheet 2
- BATT_INPUT
- 165.10, 92.71
- MOTOR_PHASE
sheet 4
- Bypass, place next to VDD pins
